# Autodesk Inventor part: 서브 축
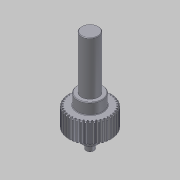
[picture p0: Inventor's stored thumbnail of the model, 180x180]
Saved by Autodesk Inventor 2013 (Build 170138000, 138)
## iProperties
Created: 2014-07
Part Number: 서브 축
Material: Steel
Document SubType Name: Modeling
Designer: KYOUNG IL JANG
Categories: <?xml version="1.0" encoding="UTF-16"?> <MemberInstance><Categories><FamilyTemplate><FamilyTemplateParameter ValueType="xs:double" Id="1" ObjectReferenceKey="da
Density: 1 g/cm^3
CustomPartVersion: 1
Company: 한국ATC센터
Author: KYOUNG IL JANG
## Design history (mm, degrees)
sketch "Sketch1"
  geometry: C1 r 21 at (0, 0)
  constraints: 1 centre point
  dimensions: "d0" = 42 diameter of C1 (= da_da)
extrude "Extrusion1" new body sketch "Sketch1" distance "d1" = 20 (= da_b); taper "d2" = 0 deg
workplane "Work Plane2"
sketch "Sketch2"
  geometry: C1 r 21 at (0, 0) reference; C2 r 20 at (0, 0)
  constraints: 1 centre point, 1 coincident
  dimensions: "d3" = 40 diameter of C2 (= da_dw)
feature "피치 지름" sketch "Sketch2" dims "d4" = 10, "d5" = 0
workplane "Work Plane8"
workplane "Work Plane9"
chamfer "모따기1" distance "d49" = 1; stored, may be unused: second distance "d50" = 2, angle "d51" = 45 deg
sketch "스케치3"
  geometry: C1 r 12.5 at (0, 0); 1 further point
  constraints: 1 centre point, 1 coincident
  dimensions: "d52" = 25 diameter of C1
extrude "돌출2" join sketch "스케치3" distance "d53" = 11; taper "d54" = 0 deg
sketch "스케치4"
  geometry: C1 r 8.5 at (0, 0); 1 further point
  constraints: 1 centre point, 1 coincident
  dimensions: "d55" = 17 diameter of C1
extrude "돌출3" join sketch "스케치4" distance "d56" = 53; taper "d57" = 0 deg
sketch "스케치5"
  geometry: C1 r 7.5 at (0, 0); 1 further point
  constraints: 1 centre point, 1 coincident
  dimensions: "d62" = 15 diameter of C1
extrude "돌출4" join sketch "스케치5" distance "d63" = 11; taper "d64" = 0 deg
sketch "스케치6"
  geometry: C1 r 4 at (0, 0); 1 further point
  constraints: 1 centre point, 1 coincident
  dimensions: "d65" = 8 diameter of C1
extrude "돌출5" join sketch "스케치6" distance "d66" = 7; taper "d67" = 0 deg
chamfer "모따기2" distance "d58" = 0.5; stored, may be unused: second distance "d59" = 2, angle "d60" = 45 deg
fillet "모깎기1" dims "d61" = 0.5
feature "스퍼 기어" dims "da_b" = 20, "da_d" = 40, "da_aw" = 31, "da_da" = 42, "da_df" = 37.5, "da_dw" = 40, angle "da_beta" = 0 deg, "da_lefttooth" = 0, "da_righttooth" = 0
body "Solid1"
body "Srf1"
other parameters: "d16" = 31 (= da_aw), "d17" = 0, "d34" = 4.5 deg (computed from da_z), "d39" = 0, "d41" = 0, "d43" = 31 (= da_aw), "d46" = 31 (= da_aw), "d47" = 0, "d48" = 0
